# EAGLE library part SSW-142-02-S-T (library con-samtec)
THROUGH-HOLE .025" SQ POST SOCKET Source: Samtec SSW.pdf
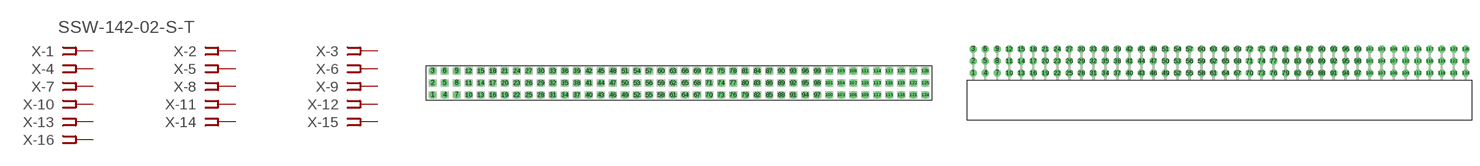
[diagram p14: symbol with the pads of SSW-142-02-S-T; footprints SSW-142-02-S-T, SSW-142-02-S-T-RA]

Designator prefix X; gates -1=FPINV -2=FPIN -3=FPIN -4=FPIN -5=FPIN -6=FPIN -7=FPIN -8=FPIN -9=FPIN -10=FPIN -11=FPIN -12=FPIN -13=FPIN -14=FPIN -15=FPIN -16=FPIN -17=FPIN -18=FPIN -19=FPIN -20=FPIN -21=FPIN -22=FPIN -23=FPIN -24=FPIN -25=FPIN -26=FPIN -27=FPIN -28=FPIN -29=FPIN -30=FPIN -31=FPIN -32=FPIN -33=FPIN -34=FPIN -35=FPIN -36=FPIN -37=FPIN -38=FPIN -39=FPIN -40=FPIN -41=FPIN -42=FPIN -43=FPIN -44=FPIN -45=FPIN -46=FPIN -47=FPIN -48=FPIN -49=FPIN -50=FPIN -51=FPIN -52=FPIN -53=FPIN -54=FPIN -55=FPIN -56=FPIN -57=FPIN -58=FPIN -59=FPIN -60=FPIN -61=FPIN -62=FPIN -63=FPIN -64=FPIN -65=FPIN -66=FPIN -67=FPIN -68=FPIN -69=FPIN -70=FPIN -71=FPIN -72=FPIN -73=FPIN -74=FPIN -75=FPIN -76=FPIN -77=FPIN -78=FPIN -79=FPIN -80=FPIN -81=FPIN -82=FPIN -83=FPIN -84=FPIN -85=FPIN -86=FPIN -87=FPIN -88=FPIN -89=FPIN -90=FPIN -91=FPIN -92=FPIN -93=FPIN -94=FPIN -95=FPIN -96=FPIN -97=FPIN -98=FPIN -99=FPIN -100=FPIN -101=FPIN -102=FPIN -103=FPIN -104=FPIN -105=FPIN -106=FPIN -107=FPIN -108=FPIN -109=FPIN -110=FPIN -111=FPIN -112=FPIN -113=FPIN -114=FPIN -115=FPIN -116=FPIN -117=FPIN -118=FPIN -119=FPIN -120=FPIN -121=FPIN -122=FPIN -123=FPIN -124=FPIN -125=FPIN -126=FPIN

## SSW-142-02-S-T (OC_FARNELL: unknown; OC_NEWARK: unknown)  [SSW-142-02-S-T]
1  -1:1  pas
2  -2:1  pas
3  -3:1  pas
4  -4:1  pas
5  -5:1  pas
6  -6:1  pas
7  -7:1  pas
8  -8:1  pas
9  -9:1  pas
10  -10:1  pas
11  -11:1  pas
12  -12:1  pas
13  -13:1  pas
14  -14:1  pas
15  -15:1  pas
16  -16:1  pas
17  -17:1  pas
18  -18:1  pas
19  -19:1  pas
20  -20:1  pas
21  -21:1  pas
22  -22:1  pas
23  -23:1  pas
24  -24:1  pas
25  -25:1  pas
26  -26:1  pas
27  -27:1  pas
28  -28:1  pas
29  -29:1  pas
30  -30:1  pas
31  -31:1  pas
32  -32:1  pas
33  -33:1  pas
34  -34:1  pas
35  -35:1  pas
36  -36:1  pas
37  -37:1  pas
38  -38:1  pas
39  -39:1  pas
40  -40:1  pas
41  -41:1  pas
42  -42:1  pas
43  -43:1  pas
44  -44:1  pas
45  -45:1  pas
46  -46:1  pas
47  -47:1  pas
48  -48:1  pas
49  -49:1  pas
50  -50:1  pas
51  -51:1  pas
52  -52:1  pas
53  -53:1  pas
54  -54:1  pas
55  -55:1  pas
56  -56:1  pas
57  -57:1  pas
58  -58:1  pas
59  -59:1  pas
60  -60:1  pas
61  -61:1  pas
62  -62:1  pas
63  -63:1  pas
64  -64:1  pas
65  -65:1  pas
66  -66:1  pas
67  -67:1  pas
68  -68:1  pas
69  -69:1  pas
70  -70:1  pas
71  -71:1  pas
72  -72:1  pas
73  -73:1  pas
74  -74:1  pas
75  -75:1  pas
76  -76:1  pas
77  -77:1  pas
78  -78:1  pas
79  -79:1  pas
80  -80:1  pas
81  -81:1  pas
82  -82:1  pas
83  -83:1  pas
84  -84:1  pas
85  -85:1  pas
86  -86:1  pas
87  -87:1  pas
88  -88:1  pas
89  -89:1  pas
90  -90:1  pas
91  -91:1  pas
92  -92:1  pas
93  -93:1  pas
94  -94:1  pas
95  -95:1  pas
96  -96:1  pas
97  -97:1  pas
98  -98:1  pas
99  -99:1  pas
100  -100:1  pas
101  -101:1  pas
102  -102:1  pas
103  -103:1  pas
104  -104:1  pas
105  -105:1  pas
106  -106:1  pas
107  -107:1  pas
108  -108:1  pas
109  -109:1  pas
110  -110:1  pas
111  -111:1  pas
112  -112:1  pas
113  -113:1  pas
114  -114:1  pas
115  -115:1  pas
116  -116:1  pas
117  -117:1  pas
118  -118:1  pas
119  -119:1  pas
120  -120:1  pas
121  -121:1  pas
122  -122:1  pas
123  -123:1  pas
124  -124:1  pas
125  -125:1  pas
126  -126:1  pas

## SSW-142-02-S-TRA (OC_FARNELL: unknown; OC_NEWARK: unknown)  [SSW-142-02-S-T-RA]
Pads as for SSW-142-02-S-T

## Footprint SSW-142-02-S-T (pad centres in mm)
THROUGH-HOLE .025" SQ POST SOCKET Source: Samtec SSW.pdf
drill 1 pad 1.5 octagon: 1 -52.07,-2.54; 2 -52.07,0; 3 -52.07,2.54; 4 -49.53,-2.54; 5 -49.53,0; 6 -49.53,2.54; 7 -46.99,-2.54; 8 -46.99,0; 9 -46.99,2.54; 10 -44.45,-2.54; 11 -44.45,0; 12 -44.45,2.54; 13 -41.91,-2.54; 14 -41.91,0; 15 -41.91,2.54; 16 -39.37,-2.54; 17 -39.37,0; 18 -39.37,2.54; 19 -36.83,-2.54; 20 -36.83,0; 21 -36.83,2.54; 22 -34.29,-2.54; 23 -34.29,0; 24 -34.29,2.54; 25 -31.75,-2.54; 26 -31.75,0; 27 -31.75,2.54; 28 -29.21,-2.54; 29 -29.21,0; 30 -29.21,2.54; 31 -26.67,-2.54; 32 -26.67,0; 33 -26.67,2.54; 34 -24.13,-2.54; 35 -24.13,0; 36 -24.13,2.54; 37 -21.59,-2.54; 38 -21.59,0; 39 -21.59,2.54; 40 -19.05,-2.54; 41 -19.05,0; 42 -19.05,2.54; 43 -16.51,-2.54; 44 -16.51,0; 45 -16.51,2.54; 46 -13.97,-2.54; 47 -13.97,0; 48 -13.97,2.54; 49 -11.43,-2.54; 50 -11.43,0; 51 -11.43,2.54; 52 -8.89,-2.54; 53 -8.89,0; 54 -8.89,2.54; 55 -6.35,-2.54; 56 -6.35,0; 57 -6.35,2.54; 58 -3.81,-2.54; 59 -3.81,0; 60 -3.81,2.54; 61 -1.27,-2.54; 62 -1.27,0; 63 -1.27,2.54; 64 1.27,-2.54; 65 1.27,0; 66 1.27,2.54; 67 3.81,-2.54; 68 3.81,0; 69 3.81,2.54; 70 6.35,-2.54; 71 6.35,0; 72 6.35,2.54; 73 8.89,-2.54; 74 8.89,0; 75 8.89,2.54; 76 11.43,-2.54; 77 11.43,0; 78 11.43,2.54; 79 13.97,-2.54; 80 13.97,0; 81 13.97,2.54; 82 16.51,-2.54; 83 16.51,0; 84 16.51,2.54; 85 19.05,-2.54; 86 19.05,0; 87 19.05,2.54; 88 21.59,-2.54; 89 21.59,0; 90 21.59,2.54; 91 24.13,-2.54; 92 24.13,0; 93 24.13,2.54; 94 26.67,-2.54; 95 26.67,0; 96 26.67,2.54; 97 29.21,-2.54; 98 29.21,0; 99 29.21,2.54; 100 31.75,-2.54; 101 31.75,0; 102 31.75,2.54; 103 34.29,-2.54; 104 34.29,0; 105 34.29,2.54; 106 36.83,-2.54; 107 36.83,0; 108 36.83,2.54; 109 39.37,-2.54; 110 39.37,0; 111 39.37,2.54; 112 41.91,-2.54; 113 41.91,0; 114 41.91,2.54; 115 44.45,-2.54; 116 44.45,0; 117 44.45,2.54; 118 46.99,-2.54; 119 46.99,0; 120 46.99,2.54; 121 49.53,-2.54; 122 49.53,0; 123 49.53,2.54; 124 52.07,-2.54; 125 52.07,0; 126 52.07,2.54

## Footprint SSW-142-02-S-T-RA (pad centres in mm)
THROUGH-HOLE .025" SQ POST SOCKET Source: Samtec SSW.pdf
drill 1 pad 1.5 octagon: 1 -52.07,1.524; 2 -52.07,4.064; 3 -52.07,6.604; 4 -49.53,1.524; 5 -49.53,4.064; 6 -49.53,6.604; 7 -46.99,1.524; 8 -46.99,4.064; 9 -46.99,6.604; 10 -44.45,1.524; 11 -44.45,4.064; 12 -44.45,6.604; 13 -41.91,1.524; 14 -41.91,4.064; 15 -41.91,6.604; 16 -39.37,1.524; 17 -39.37,4.064; 18 -39.37,6.604; 19 -36.83,1.524; 20 -36.83,4.064; 21 -36.83,6.604; 22 -34.29,1.524; 23 -34.29,4.064; 24 -34.29,6.604; 25 -31.75,1.524; 26 -31.75,4.064; 27 -31.75,6.604; 28 -29.21,1.524; 29 -29.21,4.064; 30 -29.21,6.604; 31 -26.67,1.524; 32 -26.67,4.064; 33 -26.67,6.604; 34 -24.13,1.524; 35 -24.13,4.064; 36 -24.13,6.604; 37 -21.59,1.524; 38 -21.59,4.064; 39 -21.59,6.604; 40 -19.05,1.524; 41 -19.05,4.064; 42 -19.05,6.604; 43 -16.51,1.524; 44 -16.51,4.064; 45 -16.51,6.604; 46 -13.97,1.524; 47 -13.97,4.064; 48 -13.97,6.604; 49 -11.43,1.524; 50 -11.43,4.064; 51 -11.43,6.604; 52 -8.89,1.524; 53 -8.89,4.064; 54 -8.89,6.604; 55 -6.35,1.524; 56 -6.35,4.064; 57 -6.35,6.604; 58 -3.81,1.524; 59 -3.81,4.064; 60 -3.81,6.604; 61 -1.27,1.524; 62 -1.27,4.064; 63 -1.27,6.604; 64 1.27,1.524; 65 1.27,4.064; 66 1.27,6.604; 67 3.81,1.524; 68 3.81,4.064; 69 3.81,6.604; 70 6.35,1.524; 71 6.35,4.064; 72 6.35,6.604; 73 8.89,1.524; 74 8.89,4.064; 75 8.89,6.604; 76 11.43,1.524; 77 11.43,4.064; 78 11.43,6.604; 79 13.97,1.524; 80 13.97,4.064; 81 13.97,6.604; 82 16.51,1.524; 83 16.51,4.064; 84 16.51,6.604; 85 19.05,1.524; 86 19.05,4.064; 87 19.05,6.604; 88 21.59,1.524; 89 21.59,4.064; 90 21.59,6.604; 91 24.13,1.524; 92 24.13,4.064; 93 24.13,6.604; 94 26.67,1.524; 95 26.67,4.064; 96 26.67,6.604; 97 29.21,1.524; 98 29.21,4.064; 99 29.21,6.604; 100 31.75,1.524; 101 31.75,4.064; 102 31.75,6.604; 103 34.29,1.524; 104 34.29,4.064; 105 34.29,6.604; 106 36.83,1.524; 107 36.83,4.064; 108 36.83,6.604; 109 39.37,1.524; 110 39.37,4.064; 111 39.37,6.604; 112 41.91,1.524; 113 41.91,4.064; 114 41.91,6.604; 115 44.45,1.524; 116 44.45,4.064; 117 44.45,6.604; 118 46.99,1.524; 119 46.99,4.064; 120 46.99,6.604; 121 49.53,1.524; 122 49.53,4.064; 123 49.53,6.604; 124 52.07,1.524; 125 52.07,4.064; 126 52.07,6.604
